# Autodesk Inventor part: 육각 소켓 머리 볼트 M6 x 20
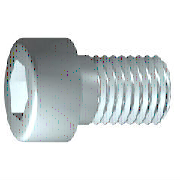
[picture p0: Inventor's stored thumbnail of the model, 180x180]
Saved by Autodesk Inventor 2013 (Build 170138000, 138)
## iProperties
IsCustomPart: 1
Created: 2012-02
Part Number: 육각 소켓 머리 볼트 M6 x 20
Material: 강철, 연강
Description: 6각 소켓 머리 캡 나사
Document SubType Name: Modeling
Standard: ISO 4762
Designer: mdu-01
Standard Revision: Fourth edition 2004-03-01
Standards Organization: ISO
Language: ko-KR
Size Designation: M6 x 20
Categories: <MemberInstance><Categories><Category DisplayName="조임쇠" InternalName="e4da775c-781d-43d5-af7c-5136215cf5a6" Mnemonic="FSTN"><Category DisplayName="볼트" InternalN
Density: 7.75 g/cm^3
Author: mdu-01
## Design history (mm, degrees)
sketch "스케치1"
  geometry: L1 (-1.333, 0)-(20, 0); L2 (20, 0)-(20, 3); L3 (20, 3)-(2.5, 3); L4 (2.5, 3)-(1.886, 3); L5 (1.886, 3)-(0, 3); L6 (0, 3)-(0, 5); L7 (0, 5)-(-6, 5); L8 (-6, 5)-(-6, 2.887); L9 (-6, 2.887)-(-3, 2.887); L10 (-3, 2.887)-(-1.333, 0); L11 (-11.2, 0)-(25.2, 0) reference; L12 (0, -1)-(0, 6) reference; L13 (2.5, 3)-(0, 3)
  constraints: 22 end point, 6 parallel, 2 collinear, 2 perpendicular, 1 horizontal, 1 point on line
  dimensions: "d1" = 17.5 distance from line of L3.end L2 (= GEL); "d2" = 0.61355 distance of L4.end L3.end (computed from GAL); "d3" = 6 distance between parallel lines of L8 L6 (= KOH); "d4" = 3 distance of L8.end L9.end (= INTI); "d5" = 60 deg angle of L10 L1; "d6" = 6 diameter of L3 L1 (= GD); "d7" = 6 diameter of L5 L1 (= BDM); "d8" = 5.7735 diameter of L9 L1 (= 1.1547 x SW); "d9" = 10 diameter of L7 L1 (= KOD); "d26" = 20 distance between parallel lines of L12 L2 (= NLG)
revolve "본체" sketch "스케치1" stored, may be unused: angle "d10" = 90 deg
sketch "스케치2"
  geometry: L1 (0, -7)-(0, 7) reference; L2 (-7, 0)-(7, 0) reference; L3 (2.887, 0)-(1.443, -2.5); L4 (1.443, -2.5)-(-1.443, -2.5); L5 (-1.443, -2.5)-(-2.887, 0); L6 (-2.887, 0)-(-1.443, 2.5); L7 (-1.443, 2.5)-(1.443, 2.5); L8 (1.443, 2.5)-(2.887, 0); 2 further points
  constraints: 12 end point, 1 coincident, 1 horizontal alignment, 1 point on line, 12 other
extrude "슬롯" join sketch "스케치2" stored distance "d11" = 10; taper "d12" = 0 deg
workplane "Work Plane1"
fillet "Fillet2" dims "d30" = 0.1 (= R)
body "Solid1"
fillet "모깎기1" dims "d17" = 0.6 (= RR)
feature "스레드" dims "d13" = 17.5 (= GEL), "d14" = 0
chamfer "모따기1" distance "d15" = 0.61345 (= -0.5 x SPD + 0.5 x GD); stored, may be unused: second distance "d16" = 0.61345 (= GUL), angle "d27" = 45 deg
other parameters: "GD" = 6 [user parameter; used in 2 equation terms], "NLG" = 20 [user parameter; used in 1 equation term], "GEL" = 17.5 [user parameter; used in 2 equation terms], "KOD" = 10 [user parameter; used in 1 equation term], "KOH" = 6 [user parameter; used in 1 equation term], "INTI" = 3 [user parameter; used in 1 equation term], "GAL" = 0.61345 (= 0.61345 x PTC) [user parameter; used in 1 equation term], "GUL" = 0.61345 (= 0.61345 x PTC) [user parameter; used in 1 equation term], "BDM" = 6 (= NND) [user parameter; used in 1 equation term], "SW" = 5 [user parameter; used in 2 equation terms], "RR" = 0.6 [user parameter; used in 1 equation term], "SPD" = 4.7731 (= NND - 1.2269 x PTC) [user parameter; used in 1 equation term], "d19" = 0, "d28" = 0, "d29" = 0, "R" = 0.1 [user parameter; used in 1 equation term], "TOA" = 30 deg [user parameter], "GD1" = 4.7731 (= THREADDIA - 1.2269 x PTC) [user parameter], "THREADDIA" = 6 [user parameter; used in 1 equation term], "FAWI" = 45 deg [user parameter], "PTC" = 1 [user parameter; used in 5 equation terms], "NND" = 6 [user parameter; used in 2 equation terms], "E0" = 5.775 (= 1.155 x SW) [user parameter]
